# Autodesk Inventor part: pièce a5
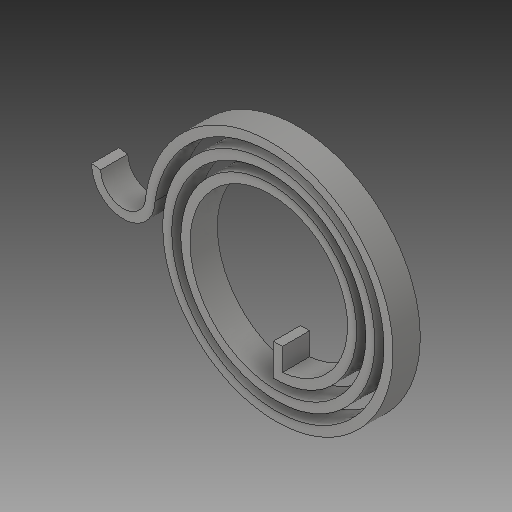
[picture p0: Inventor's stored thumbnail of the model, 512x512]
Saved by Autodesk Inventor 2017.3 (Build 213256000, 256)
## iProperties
Created: 2007-12
Part Number: pièce a5
Material: solidworks materials|Acier inoxydable moulé|6
Document SubType Name: Modeling
Designer: ficho
Appearance: 128,128,128
Author: ficho
Sending System: SolidWorks 2009
Last Author: christophe
Last Saved: 2011-01-23
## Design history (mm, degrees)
feature "Congé1"
node "Solide1"
